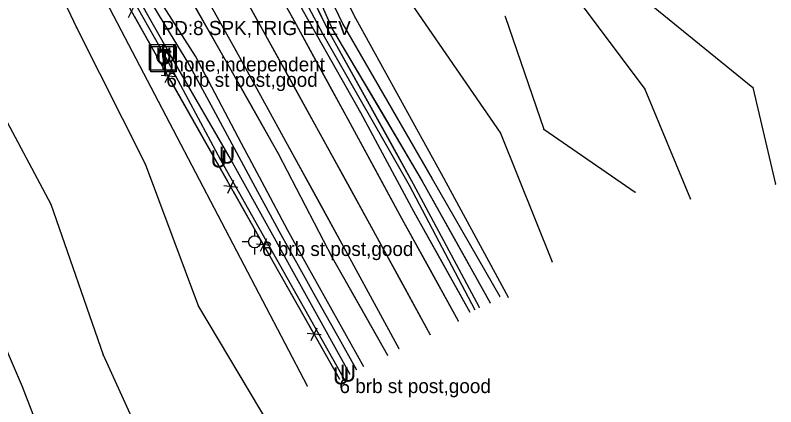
# Model space of a CAD drawing. Extents: x -99999 to 591807, y -99999 to 347168.
# Drawn here: x 589172.2 to 589441.1, y 343667.4 to 343805.9 of the extents above; entities that cross this region are included whole.
import ezdxf

# ---------------------------------------------------------------- set-up
doc = ezdxf.new("R2010")
doc.units = 0
for name, color, linetype in [('S_BREAKLINE', 7, 'Continuous'), ('S_DITCHLINE', 7, 'Continuous'), ('S_EDGE_PAVEMENT', 7, 'Continuous'), ('S_FENCE', 7, 'Continuous'), ('S_FENCE_ANNOT', 7, 'Continuous'), ('S_GRD_PT_SYM', 7, 'Continuous'), ('S_MSC_PT_SYM', 7, 'Continuous'), ('S_PAVEMENT_CROWN', 7, 'Continuous'), ('S_RDW_PT_SYM', 7, 'Continuous'), ('S_SECONDARY_CTL_ANNOT', 7, 'Continuous'), ('S_SHOULDER', 7, 'Continuous'), ('S_TELEPHONE_UTILITIES', 7, 'Continuous'), ('S_TELEPHONE_UTILITIES_ANNOT', 7, 'Continuous'), ('S_UNDERGROUND_CABLE', 7, 'Continuous'), ('S_UTILITY_POLE', 7, 'Continuous'), ('S_UTL_PT_SYM', 7, 'Continuous'), ('S_WATER_UTILITIES', 7, 'Continuous')]:
    doc.layers.add(name, color=color, linetype=linetype)

msp = doc.modelspace()

# ---------------------------------------------------------------- linework, layer by layer
at = {"layer": 'S_BREAKLINE'}
for points in [[(589259.57, 344046.86), (589287.11, 344015.19), (589313.28, 343975.46), (589338.65, 343911.32), (589374.69, 343882.79), (589378.86, 343824.38), (589432.98, 343780.35), (589441.02, 343746.15)], [(589248.17, 344040.35), (589270.79, 344017.64), (589289.75, 343972.81), (589333.96, 343912.31), (589354.61, 343881.98), (589359.54, 343826.86), (589394.77, 343779.7), (589410.93, 343740.86)], [(589122.45, 343935.59), (589160.09, 343872.72), (589193.87, 343801.51), (589218.18, 343753.31), (589237.08, 343702.89), (589262.29, 343660.54)], [(589089.66, 343924.69), (589132.38, 343857.64), (589158.55, 343788.24), (589184.84, 343739), (589203.3, 343685.76), (589223.79, 343640.59)], [(589052.22, 343921.64), (589101.97, 343846.15), (589127.03, 343776.07), (589154.37, 343721.96), (589174.68, 343674.57), (589195.94, 343619.47)], [(589307.83, 343917.09), (589276.8, 343918.85), (589234.94, 343915.87), (589255.44, 343872.29), (589279.54, 343830.17), (589292.52, 343804.79), (589322.97, 343749.69), (589346.46, 343706.11)], [(589265.56, 343917.72), (589282.37, 343883.12), (589299.06, 343829.08), (589343.81, 343764.17), (589361.97, 343718.71)], [(589219.72, 343913.97), (589243.69, 343867.82), (589265.54, 343828.39), (589280.92, 343799.18), (589311.54, 343745.76), (589334.69, 343701.69)], [(589253.1, 343871.68), (589274.76, 343830.48), (589288.07, 343802.75), (589319.56, 343748.04), (589343.5, 343706.4)], [(589345.46, 343805.37), (589359.04, 343765.54), (589391.4, 343743.29)]]:
    msp.add_lwpolyline(points, dxfattribs=at)
at = {"layer": 'S_DITCHLINE'}
for points in [[(589292.94, 343680.41), (589286.28, 343692.36), (589279.61, 343704.3), (589272.94, 343716.24), (589266.27, 343728.19), (589258, 343743.46), (589249.73, 343758.73), (589241.46, 343774.01), (589233.2, 343789.28), (589223.25, 343805.72), (589213.31, 343822.15), (589203.36, 343838.59), (589193.42, 343855.02), (589183.84, 343872.75), (589174.25, 343890.49), (589164.67, 343908.22), (589155.08, 343925.95), (589144.54, 343945.21)], [(589295.45, 343681.5), (589288.73, 343693.55), (589282.01, 343705.59), (589275.29, 343717.64), (589268.57, 343729.69), (589260.42, 343745.11), (589252.28, 343760.52), (589244.14, 343775.94), (589236, 343791.36), (589225.75, 343807.46), (589215.5, 343823.56), (589205.26, 343839.67), (589195.01, 343855.77), (589185.74, 343873.6), (589176.46, 343891.43), (589167.19, 343909.26), (589157.92, 343927.09), (589145.7, 343945.78)], [(589225.56, 343915.88), (589249.83, 343870.46), (589271.45, 343830.32), (589284.4, 343800.85), (589316.11, 343747.23), (589340.1, 343704.21)], [(589225.56, 343915.88), (589231.63, 343904.53), (589237.69, 343893.17), (589243.76, 343881.81), (589249.83, 343870.46), (589260.64, 343850.39), (589271.45, 343830.32), (589277.92, 343815.59), (589284.4, 343800.85), (589292.32, 343787.45), (589300.25, 343774.04), (589308.18, 343760.64), (589316.11, 343747.23), (589328.1, 343725.72), (589340.1, 343704.21)], [(589222.45, 343914.18), (589246.28, 343869.21), (589268.61, 343829.63), (589282.91, 343800.45), (589312.93, 343746.22), (589336.25, 343702.58)], [(589222.45, 343914.18), (589228.41, 343902.94), (589234.36, 343891.69), (589240.32, 343880.45), (589246.28, 343869.21), (589257.45, 343849.42), (589268.61, 343829.63), (589275.76, 343815.04), (589282.91, 343800.45), (589290.42, 343786.89), (589297.92, 343773.34), (589305.43, 343759.78), (589312.93, 343746.22), (589324.59, 343724.4), (589336.25, 343702.58)]]:
    msp.add_lwpolyline(points, dxfattribs=at)
at = {"layer": 'S_EDGE_PAVEMENT'}
for points in [[(589044.06, 344210.38), (589062.61, 344176.98), (589089.04, 344129.8), (589108.67, 344094.28), (589125.56, 344064.19), (589145.2, 344028.97), (589161.69, 343999.91), (589175.36, 343974.71), (589194.37, 343940.44), (589208.05, 343916.06), (589231.37, 343874.53), (589249.48, 343841.72), (589270.08, 343805.14), (589289.8, 343769.16), (589308.91, 343733.9), (589328.84, 343697.75)], [(589023.86, 344198.7), (589042.88, 344164.72), (589068.45, 344118.72), (589088.8, 344082.18), (589106.8, 344049.99), (589124.92, 344017.73), (589142.03, 343987.05), (589155.39, 343963.21), (589174.41, 343928.82), (589188.27, 343903.72), (589210.34, 343864.33), (589229.44, 343830.56), (589250.2, 343793.38), (589269.11, 343758.95), (589288.96, 343722.64), (589307.86, 343688.02)], [(589148.71, 343975.13), (589155.39, 343963.21), (589164.9, 343946.02), (589174.41, 343928.82), (589181.34, 343916.27), (589188.27, 343903.72), (589199.31, 343884.03), (589210.34, 343864.33), (589219.89, 343847.44), (589229.44, 343830.56), (589239.82, 343811.97), (589250.2, 343793.38), (589259.65, 343776.17), (589269.11, 343758.95), (589279.03, 343740.79), (589288.96, 343722.64), (589298.41, 343705.33), (589307.86, 343688.02)], [(589175.36, 343974.71), (589184.86, 343957.58), (589194.37, 343940.44), (589201.21, 343928.25), (589208.05, 343916.06), (589219.71, 343895.3), (589231.37, 343874.53), (589240.42, 343858.13), (589249.48, 343841.72), (589259.78, 343823.43), (589270.08, 343805.14), (589279.94, 343787.15), (589289.8, 343769.16), (589299.35, 343751.53), (589308.91, 343733.9), (589318.88, 343715.83), (589328.84, 343697.75)]]:
    msp.add_lwpolyline(points, dxfattribs=at)
at = {"layer": 'S_FENCE'}
for p, q in [((589225.65, 343785.56), (589188.11, 343852.27)), ((589212.32, 343805.07), (589214.49, 343809.58)), ((589225.3, 343782.03), (589227.45, 343786.54)), ((589259.46, 343725.73), (589225.65, 343785.56)), ((589228.86, 343784.05), (589223.88, 343784.53)), ((589250.92, 343745.01), (589245.94, 343745.49)), ((589247.35, 343742.99), (589249.51, 343747.51)), ((589258.97, 343722.44), (589261.12, 343726.96)), ((589262.53, 343724.46), (589257.55, 343724.94)), ((589286.85, 343677.25), (589259.46, 343725.73)), ((589276.84, 343690.81), (589278.99, 343695.32)), ((589280.4, 343692.83), (589275.42, 343693.31))]:
    msp.add_line(p, q, dxfattribs=at)
for points in [[(589225.65, 343785.56), (589214.52, 343805.35)], [(589247.43, 343747.02), (589227.38, 343782.51)], [(589259.46, 343725.73), (589249.43, 343743.48)], [(589277.1, 343694.51), (589260.86, 343723.26)], [(589286.85, 343677.25), (589278.73, 343691.63)]]:
    msp.add_lwpolyline(points, dxfattribs=at)
at = {"layer": 'S_GRD_PT_SYM'}
for points in [[(589292.52, 343804.79), (589292.57, 343804.81), (589292.52, 343804.79), (589292.5, 343804.83), (589292.52, 343804.79), (589292.48, 343804.76), (589292.52, 343804.79), (589292.55, 343804.74)], [(589345.46, 343805.37), (589345.51, 343805.39), (589345.46, 343805.37), (589345.45, 343805.42), (589345.46, 343805.37), (589345.42, 343805.35), (589345.46, 343805.37), (589345.48, 343805.32)], [(589288.07, 343802.75), (589288.11, 343802.78), (589288.07, 343802.75), (589288.04, 343802.8), (589288.07, 343802.75), (589288.03, 343802.73), (589288.07, 343802.75), (589288.09, 343802.71)], [(589193.87, 343801.51), (589193.92, 343801.53), (589193.87, 343801.51), (589193.85, 343801.55), (589193.87, 343801.51), (589193.83, 343801.49), (589193.87, 343801.51), (589193.9, 343801.46)], [(589280.92, 343799.18), (589280.96, 343799.21), (589280.92, 343799.18), (589280.89, 343799.23), (589280.92, 343799.18), (589280.88, 343799.16), (589280.92, 343799.18), (589280.94, 343799.14)], [(589282.91, 343800.45), (589282.95, 343800.47), (589282.91, 343800.45), (589282.89, 343800.49), (589282.91, 343800.45), (589282.87, 343800.42), (589282.91, 343800.45), (589282.93, 343800.4)], [(589284.4, 343800.85), (589284.44, 343800.88), (589284.4, 343800.85), (589284.37, 343800.9), (589284.4, 343800.85), (589284.35, 343800.83), (589284.4, 343800.85), (589284.42, 343800.81)], [(589432.98, 343780.35), (589433.02, 343780.36), (589432.98, 343780.35), (589432.96, 343780.4), (589432.98, 343780.35), (589432.93, 343780.34), (589432.98, 343780.35), (589432.99, 343780.3)], [(589394.77, 343779.7), (589394.81, 343779.72), (589394.77, 343779.7), (589394.75, 343779.75), (589394.77, 343779.7), (589394.72, 343779.69), (589394.77, 343779.7), (589394.79, 343779.66)], [(589343.81, 343764.17), (589343.86, 343764.19), (589343.81, 343764.17), (589343.8, 343764.21), (589343.81, 343764.17), (589343.77, 343764.15), (589343.81, 343764.17), (589343.83, 343764.12)], [(589359.04, 343765.54), (589359.06, 343765.58), (589359.04, 343765.54), (589358.99, 343765.57), (589359.04, 343765.54), (589359.01, 343765.5), (589359.04, 343765.54), (589359.08, 343765.51)], [(589218.18, 343753.31), (589218.23, 343753.32), (589218.18, 343753.31), (589218.16, 343753.35), (589218.18, 343753.31), (589218.13, 343753.29), (589218.18, 343753.31), (589218.2, 343753.26)], [(589319.56, 343748.04), (589319.6, 343748.06), (589319.56, 343748.04), (589319.54, 343748.08), (589319.56, 343748.04), (589319.52, 343748.01), (589319.56, 343748.04), (589319.59, 343747.99)], [(589322.97, 343749.69), (589323.01, 343749.72), (589322.97, 343749.69), (589322.94, 343749.74), (589322.97, 343749.69), (589322.92, 343749.67), (589322.97, 343749.69), (589322.99, 343749.65)], [(589311.54, 343745.76), (589311.58, 343745.78), (589311.54, 343745.76), (589311.51, 343745.8), (589311.54, 343745.76), (589311.49, 343745.73), (589311.54, 343745.76), (589311.56, 343745.71)], [(589312.93, 343746.22), (589312.98, 343746.25), (589312.93, 343746.22), (589312.91, 343746.27), (589312.93, 343746.22), (589312.89, 343746.2), (589312.93, 343746.22), (589312.96, 343746.18)], [(589316.11, 343747.23), (589316.15, 343747.26), (589316.11, 343747.23), (589316.09, 343747.28), (589316.11, 343747.23), (589316.07, 343747.21), (589316.11, 343747.23), (589316.13, 343747.19)], [(589441.02, 343746.15), (589441.07, 343746.16), (589441.02, 343746.15), (589441.01, 343746.2), (589441.02, 343746.15), (589440.97, 343746.14), (589441.02, 343746.15), (589441.03, 343746.1)], [(589391.4, 343743.29), (589391.43, 343743.33), (589391.4, 343743.29), (589391.36, 343743.32), (589391.4, 343743.29), (589391.37, 343743.25), (589391.4, 343743.29), (589391.44, 343743.26)], [(589410.93, 343740.86), (589410.97, 343740.88), (589410.93, 343740.86), (589410.91, 343740.91), (589410.93, 343740.86), (589410.88, 343740.84), (589410.93, 343740.86), (589410.95, 343740.81)], [(589184.84, 343739), (589184.89, 343739.02), (589184.84, 343739), (589184.82, 343739.05), (589184.84, 343739), (589184.79, 343738.99), (589184.84, 343739), (589184.86, 343738.95)], [(589361.97, 343718.71), (589362.02, 343718.73), (589361.97, 343718.71), (589361.95, 343718.76), (589361.97, 343718.71), (589361.92, 343718.69), (589361.97, 343718.71), (589361.99, 343718.66)], [(589343.5, 343706.4), (589343.55, 343706.43), (589343.5, 343706.4), (589343.48, 343706.45), (589343.5, 343706.4), (589343.46, 343706.38), (589343.5, 343706.4), (589343.53, 343706.36)], [(589346.46, 343706.11), (589346.51, 343706.13), (589346.46, 343706.11), (589346.44, 343706.15), (589346.46, 343706.11), (589346.42, 343706.08), (589346.46, 343706.11), (589346.49, 343706.06)], [(589237.08, 343702.89), (589237.12, 343702.92), (589237.08, 343702.89), (589237.05, 343702.94), (589237.08, 343702.89), (589237.04, 343702.87), (589237.08, 343702.89), (589237.11, 343702.85)], [(589336.25, 343702.58), (589336.29, 343702.6), (589336.25, 343702.58), (589336.22, 343702.62), (589336.25, 343702.58), (589336.2, 343702.55), (589336.25, 343702.58), (589336.27, 343702.53)], [(589340.1, 343704.21), (589340.14, 343704.23), (589340.1, 343704.21), (589340.07, 343704.25), (589340.1, 343704.21), (589340.05, 343704.18), (589340.1, 343704.21), (589340.12, 343704.16)], [(589334.69, 343701.69), (589334.74, 343701.71), (589334.69, 343701.69), (589334.67, 343701.73), (589334.69, 343701.69), (589334.65, 343701.66), (589334.69, 343701.69), (589334.72, 343701.64)], [(589203.3, 343685.76), (589203.35, 343685.78), (589203.3, 343685.76), (589203.28, 343685.8), (589203.3, 343685.76), (589203.26, 343685.74), (589203.3, 343685.76), (589203.32, 343685.71)], [(589174.68, 343674.57), (589174.73, 343674.59), (589174.68, 343674.57), (589174.66, 343674.61), (589174.68, 343674.57), (589174.63, 343674.55), (589174.68, 343674.57), (589174.7, 343674.52)]]:
    msp.add_lwpolyline(points, close=True, dxfattribs=at)
at = {"layer": 'S_MSC_PT_SYM'}
for points in [[(589225.65, 343785.56), (589225.65, 343785.61), (589225.65, 343785.56), (589225.6, 343785.56), (589225.65, 343785.56), (589225.65, 343785.51), (589225.65, 343785.56), (589225.7, 343785.56)], [(589259.46, 343725.73), (589259.46, 343725.78), (589259.46, 343725.73), (589259.41, 343725.73), (589259.46, 343725.73), (589259.46, 343725.68), (589259.46, 343725.73), (589259.51, 343725.73)], [(589286.85, 343677.25), (589286.85, 343677.3), (589286.85, 343677.25), (589286.8, 343677.25), (589286.85, 343677.25), (589286.85, 343677.2), (589286.85, 343677.25), (589286.9, 343677.25)]]:
    msp.add_lwpolyline(points, dxfattribs=at)
at = {"layer": 'S_PAVEMENT_CROWN'}
for points in [[(589034.18, 344204.28), (589052.82, 344171.66), (589078.89, 344124.45), (589099.08, 344088.67), (589116.35, 344057.6), (589135.37, 344023.69), (589152.41, 343993.38), (589165.9, 343969), (589184.66, 343935.23), (589198.39, 343910.2), (589220.86, 343870.52), (589240.04, 343836.28), (589260.16, 343799.88), (589280.05, 343763.84), (589299.46, 343728.43), (589318.91, 343692.89)], [(589165.9, 343969), (589175.28, 343952.11), (589184.66, 343935.23), (589191.53, 343922.71), (589198.39, 343910.2), (589209.63, 343890.36), (589220.86, 343870.52), (589230.45, 343853.4), (589240.04, 343836.28), (589250.1, 343818.08), (589260.16, 343799.88), (589270.1, 343781.86), (589280.05, 343763.84), (589289.75, 343746.13), (589299.46, 343728.43), (589309.19, 343710.66), (589318.91, 343692.89)]]:
    msp.add_lwpolyline(points, dxfattribs=at)
at = {"layer": 'S_RDW_PT_SYM'}
for points in [[(589270.08, 343805.14), (589270.12, 343805.17), (589270.08, 343805.14), (589270.05, 343805.19), (589270.08, 343805.14), (589270.03, 343805.12), (589270.08, 343805.14), (589270.1, 343805.1)], [(589260.16, 343799.88), (589260.2, 343799.9), (589260.16, 343799.88), (589260.14, 343799.92), (589260.16, 343799.88), (589260.12, 343799.85), (589260.16, 343799.88), (589260.19, 343799.84)], [(589245.99, 343790.87), (589246.03, 343790.89), (589245.99, 343790.87), (589245.96, 343790.91), (589245.99, 343790.87), (589245.94, 343790.84), (589245.99, 343790.87), (589246.01, 343790.83)], [(589250.2, 343793.38), (589250.24, 343793.41), (589250.2, 343793.38), (589250.17, 343793.43), (589250.2, 343793.38), (589250.15, 343793.36), (589250.2, 343793.38), (589250.22, 343793.34)], [(589294.29, 343771.45), (589294.33, 343771.48), (589294.29, 343771.45), (589294.26, 343771.5), (589294.29, 343771.45), (589294.24, 343771.43), (589294.29, 343771.45), (589294.31, 343771.41)], [(589289.8, 343769.16), (589289.84, 343769.19), (589289.8, 343769.16), (589289.77, 343769.21), (589289.8, 343769.16), (589289.75, 343769.14), (589289.8, 343769.16), (589289.82, 343769.12)], [(589280.05, 343763.84), (589280.09, 343763.86), (589280.05, 343763.84), (589280.02, 343763.88), (589280.05, 343763.84), (589280, 343763.82), (589280.05, 343763.84), (589280.07, 343763.8)], [(589269.11, 343758.95), (589269.16, 343758.97), (589269.11, 343758.95), (589269.09, 343758.99), (589269.11, 343758.95), (589269.07, 343758.92), (589269.11, 343758.95), (589269.14, 343758.9)], [(589265.2, 343757.03), (589265.24, 343757.06), (589265.2, 343757.03), (589265.18, 343757.08), (589265.2, 343757.03), (589265.16, 343757.01), (589265.2, 343757.03), (589265.22, 343756.99)], [(589313.17, 343736.4), (589313.22, 343736.42), (589313.17, 343736.4), (589313.15, 343736.44), (589313.17, 343736.4), (589313.13, 343736.38), (589313.17, 343736.4), (589313.2, 343736.36)], [(589308.91, 343733.9), (589308.96, 343733.93), (589308.91, 343733.9), (589308.89, 343733.95), (589308.91, 343733.9), (589308.87, 343733.88), (589308.91, 343733.9), (589308.94, 343733.86)], [(589299.46, 343728.43), (589299.5, 343728.45), (589299.46, 343728.43), (589299.44, 343728.47), (589299.46, 343728.43), (589299.42, 343728.4), (589299.46, 343728.43), (589299.48, 343728.38)], [(589288.96, 343722.64), (589289, 343722.66), (589288.96, 343722.64), (589288.93, 343722.68), (589288.96, 343722.64), (589288.91, 343722.61), (589288.96, 343722.64), (589288.98, 343722.59)], [(589284.29, 343720.23), (589284.33, 343720.25), (589284.29, 343720.23), (589284.26, 343720.27), (589284.29, 343720.23), (589284.24, 343720.2), (589284.29, 343720.23), (589284.31, 343720.18)], [(589332.94, 343700.87), (589332.98, 343700.89), (589332.94, 343700.87), (589332.91, 343700.91), (589332.94, 343700.87), (589332.89, 343700.84), (589332.94, 343700.87), (589332.96, 343700.82)], [(589328.84, 343697.75), (589328.89, 343697.78), (589328.84, 343697.75), (589328.82, 343697.8), (589328.84, 343697.75), (589328.8, 343697.73), (589328.84, 343697.75), (589328.87, 343697.71)], [(589318.91, 343692.89), (589318.96, 343692.91), (589318.91, 343692.89), (589318.89, 343692.93), (589318.91, 343692.89), (589318.87, 343692.86), (589318.91, 343692.89), (589318.94, 343692.84)], [(589307.86, 343688.02), (589307.91, 343688.05), (589307.86, 343688.02), (589307.84, 343688.07), (589307.86, 343688.02), (589307.82, 343688), (589307.86, 343688.02), (589307.89, 343687.98)], [(589303.79, 343685.69), (589303.83, 343685.72), (589303.79, 343685.69), (589303.76, 343685.74), (589303.79, 343685.69), (589303.74, 343685.67), (589303.79, 343685.69), (589303.81, 343685.65)]]:
    msp.add_lwpolyline(points, close=True, dxfattribs=at)
at = {"layer": 'S_SHOULDER'}
for points in [[(589150.57, 343960.5), (589170.21, 343926.38), (589184.1, 343900.61), (589206.3, 343862.26), (589224.95, 343827.94), (589245.99, 343790.87), (589265.2, 343757.03), (589284.29, 343720.23), (589303.79, 343685.69)], [(589150.57, 343960.5), (589160.39, 343943.44), (589170.21, 343926.38), (589177.15, 343913.49), (589184.1, 343900.61), (589195.2, 343881.44), (589206.3, 343862.26), (589215.63, 343845.1), (589224.95, 343827.94), (589235.47, 343809.4), (589245.99, 343790.87), (589255.59, 343773.95), (589265.2, 343757.03), (589274.74, 343738.63), (589284.29, 343720.23), (589294.04, 343702.96), (589303.79, 343685.69)], [(589213.01, 343916.47), (589235.09, 343876.73), (589253.9, 343844.33), (589274.01, 343807.37), (589294.29, 343771.45), (589313.17, 343736.4), (589332.94, 343700.87)], [(589213.01, 343916.47), (589224.05, 343896.6), (589235.09, 343876.73), (589244.49, 343860.53), (589253.9, 343844.33), (589263.95, 343825.85), (589274.01, 343807.37), (589284.15, 343789.41), (589294.29, 343771.45), (589303.73, 343753.93), (589313.17, 343736.4), (589323.05, 343718.63), (589332.94, 343700.87)]]:
    msp.add_lwpolyline(points, dxfattribs=at)
at = {"layer": 'S_TELEPHONE_UTILITIES'}
for p, q in [((589224.42, 343793.08), (589224.42, 343795.21)), ((589224.42, 343788.86), (589224.42, 343786.8))]:
    msp.add_line(p, q, dxfattribs=at)
for points in [[(589219.74, 343786.49), (589219.74, 343795.49), (589228.74, 343795.49), (589228.74, 343786.49)], [(589220.18, 343785.85), (589220.18, 343794.85), (589229.18, 343794.85), (589229.18, 343785.85)]]:
    msp.add_lwpolyline(points, close=True, dxfattribs=at)
msp.add_circle((589224.44, 343791), 2.11, dxfattribs=at)
at = {"layer": 'S_UNDERGROUND_CABLE'}
for p, q in [((589225.51, 343790.96), (589147.38, 343928.99)), ((589227.16, 343791.77), (589149.15, 343929.41)), ((589244.94, 343754.6), (589225.51, 343790.96)), ((589247.86, 343755.96), (589227.16, 343791.77)), ((589290.59, 343678.85), (589247.86, 343755.96)), ((589288.16, 343677.87), (589244.94, 343754.6))]:
    msp.add_line(p, q, dxfattribs=at)
at = {"layer": 'S_UTILITY_POLE'}
for p, q in [((589256.88, 343727.84), (589256.88, 343730.09)), ((589254.78, 343725.71), (589252.46, 343725.71)), ((589256.95, 343721.29), (589256.95, 343723.62))]:
    msp.add_line(p, q, dxfattribs=at)
msp.add_circle((589256.88, 343725.73), 2.13, dxfattribs=at)
at = {"layer": 'S_UTL_PT_SYM'}
msp.add_lwpolyline([(589275.46, 343674.76), (589275.46, 343674.81), (589275.46, 343674.76), (589275.41, 343674.76), (589275.46, 343674.76), (589275.46, 343674.71), (589275.46, 343674.76), (589275.51, 343674.76)], dxfattribs=at)
at = {"layer": 'S_WATER_UTILITIES'}
msp.add_line((589204.45, 343810.59), (589275.46, 343674.76), dxfattribs=at)

# ---------------------------------------------------------------- texts
at = {"layer": 'S_FENCE_ANNOT'}
for p in [(589225.65, 343780.56), (589259.46, 343720.73), (589286.85, 343672.25)]:
    msp.add_text('6 brb st post,good', height=5, dxfattribs=at).set_placement(p)
at = {"layer": 'S_SECONDARY_CTL_ANNOT'}
msp.add_text('PD:8 SPK,TRIG ELEV', height=5, dxfattribs=at).set_placement((589223.96, 343798.85))
at = {"layer": 'S_TELEPHONE_UTILITIES'}
for p in [(589222.3, 343787.99), (589222.74, 343787.35)]:
    msp.add_text('T', height=6, rotation=360, dxfattribs=at).set_placement(p)
at = {"layer": 'S_TELEPHONE_UTILITIES_ANNOT'}
for s, p in [('phone', (589224.44, 343786)), ('phone,independent', (589224.47, 343786.01))]:
    msp.add_text(s, height=5, dxfattribs=at).set_placement(p)
at = {"layer": 'S_UTL_PT_SYM'}
for p in [(589221.88, 343788.42), (589223.53, 343789.22), (589244.23, 343753.42), (589241.31, 343752.05), (589284.53, 343675.33), (589286.96, 343676.3)]:
    msp.add_text('U', height=6, rotation=360, dxfattribs=at).set_placement(p)

doc.saveas('drawing.dxf')
